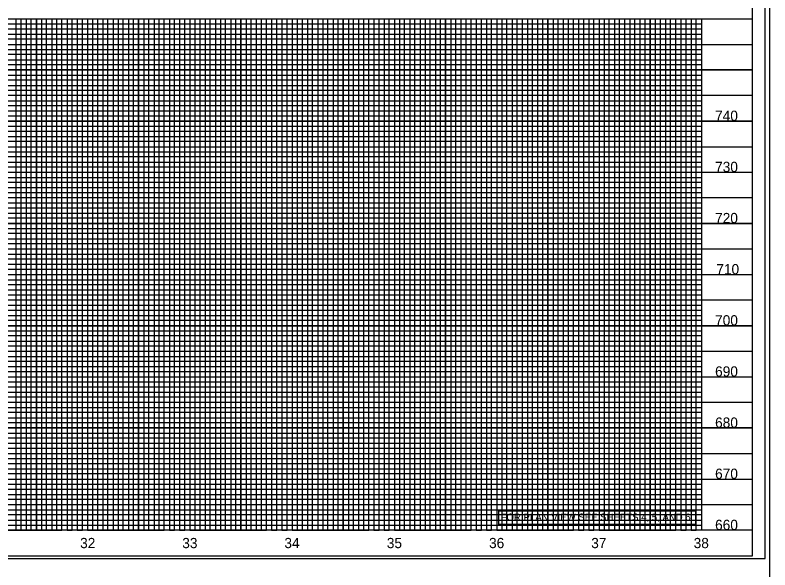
# Model space of a CAD drawing. Extents: x 1754992 to 1757273, y 732111 to 735411.
# Drawn here: x 1756127 to 1756865, y 734322 to 734864 of the extents above; entities that cross this region are included whole.
import ezdxf

# ---------------------------------------------------------------- set-up
doc = ezdxf.new("R2010")
doc.units = 0
for name, color, linetype in [('ENG SEALS CELL', 7, 'Continuous'), ('Prop DSN Text', 7, 'Continuous'), ('Scratch_Level_3', 7, 'Continuous'), ('Sheet DOT Grid CELL', 7, 'Continuous'), ('Sheet PE Seal Cell', 7, 'Continuous'), ('Sheet Plot Border Inside CELL', 7, 'Continuous'), ('Sheet Plot Border Outside CELL', 7, 'Continuous'), ('Sheet Profile CELL', 7, 'Continuous'), ('Sheet Profile Grid Major CELL', 7, 'Continuous'), ('Sheet Profile Grid Middle CELL', 7, 'Continuous'), ('Sheet Profile Grid Minor CELL', 7, 'Continuous')]:
    doc.layers.add(name, color=color, linetype=linetype)

msp = doc.modelspace()

# ---------------------------------------------------------------- linework, layer by layer
at = {"layer": 'ENG SEALS CELL'}
msp.add_lwpolyline([(1756599.59, 734379.75), (1756792.01, 734379.75), (1756792.01, 734366.55), (1756599.59, 734366.55)], close=True, dxfattribs=at)
at = {"layer": 'Scratch_Level_3'}
msp.add_lwpolyline([(1755397.67, 734860.78), (1756797.67, 734860.78), (1756797.67, 734360.78), (1755397.67, 734360.78)], close=True, dxfattribs=at)
at = {"layer": 'Sheet DOT Grid CELL'}
for p, q in [((1755347.67, 734860.78), (1756847.56, 734860.78)), ((1756147.67, 734860.78), (1756147.67, 734360.78)), ((1756197.67, 734860.78), (1756197.67, 734360.78)), ((1756247.67, 734860.78), (1756247.67, 734360.78)), ((1756297.67, 734860.78), (1756297.67, 734360.78)), ((1756347.67, 734860.78), (1756347.67, 734360.78)), ((1756397.67, 734860.78), (1756397.67, 734360.78)), ((1756447.67, 734860.78), (1756447.67, 734360.78)), ((1756497.67, 734860.78), (1756497.67, 734360.78)), ((1756547.67, 734860.78), (1756547.67, 734360.78)), ((1756597.67, 734860.78), (1756597.67, 734360.78)), ((1756647.67, 734860.78), (1756647.67, 734360.78)), ((1756697.67, 734860.78), (1756697.67, 734360.78)), ((1756747.67, 734860.78), (1756747.67, 734360.78)), ((1756797.67, 734860.78), (1756797.67, 734360.78)), ((1755347.67, 734810.78), (1756847.56, 734810.78)), ((1755347.67, 734760.78), (1756847.56, 734760.78)), ((1755347.67, 734710.78), (1756847.56, 734710.78)), ((1755347.67, 734660.78), (1756847.56, 734660.78)), ((1755347.67, 734610.78), (1756847.56, 734610.78)), ((1755347.67, 734560.78), (1756847.56, 734560.78)), ((1755347.67, 734510.78), (1756847.56, 734510.78)), ((1755347.67, 734460.78), (1756847.56, 734460.78)), ((1755347.67, 734410.78), (1756847.56, 734410.78))]:
    msp.add_line(p, q, dxfattribs=at)
at = {"layer": 'Sheet Plot Border Inside CELL'}
msp.add_lwpolyline([(1755193.67, 734333.23), (1756860.17, 734333.23), (1756860.17, 735388.33), (1755193.67, 735388.33)], close=True, dxfattribs=at)
at = {"layer": 'Sheet Plot Border Outside CELL'}
msp.add_lwpolyline([(1755180.67, 734310.78), (1756864.67, 734310.78), (1756864.67, 735410.78), (1755180.67, 735410.78)], close=True, dxfattribs=at)
at = {"layer": 'Sheet Profile CELL'}
for p, q in [((1755347.67, 734860.78), (1756847.67, 734860.78)), ((1756847.67, 734360.78), (1755347.67, 734360.78)), ((1755347.67, 734335.78), (1756847.67, 734335.78))]:
    msp.add_line(p, q, dxfattribs=at)
msp.add_lwpolyline([(1756847.67, 735385.78), (1755347.67, 735385.78), (1755347.67, 734335.78), (1756847.67, 734335.78)], close=True, dxfattribs=at)
at = {"layer": 'Sheet Profile Grid Major CELL'}
for p, q in [((1756147.67, 734860.78), (1756197.67, 734860.78)), ((1756247.67, 734860.78), (1756297.67, 734860.78)), ((1756347.67, 734860.78), (1756397.67, 734860.78)), ((1756447.67, 734860.78), (1756497.67, 734860.78)), ((1756547.67, 734860.78), (1756597.67, 734860.78)), ((1756647.67, 734860.78), (1756697.67, 734860.78)), ((1756747.67, 734860.78), (1756797.67, 734860.78)), ((1756747.67, 734360.78), (1756747.67, 734360.78))]:
    msp.add_line(p, q, dxfattribs=at)
for points in [[(1756097.67, 734360.78), (1756147.67, 734360.78), (1756147.67, 734860.78), (1756197.67, 734860.78), (1756197.67, 734360.78), (1756247.67, 734360.78), (1756247.67, 734860.78), (1756297.67, 734860.78), (1756297.67, 734360.78), (1756347.67, 734360.78), (1756347.67, 734860.78), (1756397.67, 734860.78), (1756397.67, 734360.78), (1756447.67, 734360.78), (1756447.67, 734860.78), (1756497.67, 734860.78), (1756497.67, 734360.78), (1756547.67, 734360.78), (1756547.67, 734860.78), (1756597.67, 734860.78), (1756597.67, 734360.78), (1756647.67, 734360.78), (1756647.67, 734860.78), (1756697.67, 734860.78), (1756697.67, 734360.78), (1756747.67, 734360.78), (1756747.67, 734360.78), (1756747.67, 734860.78), (1756797.67, 734860.78), (1756797.67, 734360.78)], [(1756847.67, 734810.78), (1755347.67, 734810.78)], [(1756847.67, 734760.78), (1755347.67, 734760.78), (1755347.67, 734710.78), (1756847.67, 734710.78)], [(1756847.67, 734660.78), (1755347.67, 734660.78), (1755347.67, 734610.78), (1756847.67, 734610.78)], [(1756847.67, 734560.78), (1755347.67, 734560.78), (1755347.67, 734510.78), (1756847.67, 734510.78)], [(1756847.67, 734460.78), (1755347.67, 734460.78), (1755347.67, 734460.78), (1755347.67, 734410.78), (1756847.67, 734410.78)], [(1756847.67, 734360.78), (1755347.67, 734360.78)]]:
    msp.add_lwpolyline(points, dxfattribs=at)
at = {"layer": 'Sheet Profile Grid Middle CELL'}
for points in [[(1756122.67, 734360.78), (1756172.67, 734360.78), (1756172.67, 734860.78), (1756222.67, 734860.78), (1756222.67, 734360.78), (1756272.67, 734360.78), (1756272.67, 734860.78), (1756322.67, 734860.78), (1756322.67, 734360.78), (1756372.67, 734360.78), (1756372.67, 734860.78), (1756422.67, 734860.78), (1756422.67, 734360.78), (1756472.67, 734360.78), (1756472.67, 734860.78), (1756522.67, 734860.78), (1756522.67, 734360.78), (1756572.67, 734360.78), (1756572.67, 734860.78), (1756622.67, 734860.78), (1756622.67, 734360.78), (1756672.67, 734360.78), (1756672.67, 734860.78), (1756722.67, 734860.78), (1756722.67, 734360.78), (1756772.67, 734360.78), (1756772.67, 734860.78)], [(1755347.67, 734835.78), (1756847.67, 734835.78)], [(1756847.67, 734785.78), (1755347.67, 734785.78), (1755347.67, 734735.78), (1756847.67, 734735.78)], [(1756847.67, 734685.78), (1755347.67, 734685.78), (1755347.67, 734635.78), (1756847.67, 734635.78)], [(1756847.67, 734585.78), (1755347.67, 734585.78), (1755347.67, 734535.78), (1756847.67, 734535.78)], [(1756847.67, 734485.78), (1755347.67, 734485.78), (1755347.67, 734435.78), (1756847.67, 734435.78)], [(1756847.67, 734385.78), (1755347.67, 734385.78)]]:
    msp.add_lwpolyline(points, dxfattribs=at)
at = {"layer": 'Sheet Profile Grid Minor CELL'}
for p, q in [((1755397.67, 734855.78), (1756797.67, 734855.78)), ((1756797.67, 734850.78), (1755397.67, 734850.78)), ((1755397.67, 734845.78), (1756797.67, 734845.78)), ((1756797.67, 734840.78), (1755397.67, 734840.78)), ((1755397.67, 734830.78), (1756797.67, 734830.78)), ((1756797.67, 734825.78), (1755397.67, 734825.78)), ((1755397.67, 734820.78), (1756797.67, 734820.78)), ((1756797.67, 734815.78), (1755397.67, 734815.78)), ((1755397.67, 734805.78), (1756797.67, 734805.78)), ((1756797.67, 734800.78), (1755397.67, 734800.78)), ((1755397.67, 734795.78), (1756797.67, 734795.78)), ((1756797.67, 734790.78), (1755397.67, 734790.78)), ((1755397.67, 734780.78), (1756797.67, 734780.78)), ((1756797.67, 734775.78), (1755397.67, 734775.78)), ((1755397.67, 734770.78), (1756797.67, 734770.78)), ((1756797.67, 734765.78), (1755397.67, 734765.78)), ((1755397.67, 734755.78), (1756797.67, 734755.78)), ((1756797.67, 734750.78), (1755397.67, 734750.78)), ((1755397.67, 734745.78), (1756797.67, 734745.78)), ((1756797.67, 734740.78), (1755397.67, 734740.78)), ((1755397.67, 734730.78), (1756797.67, 734730.78)), ((1756797.67, 734725.78), (1755397.67, 734725.78)), ((1755397.67, 734720.78), (1756797.67, 734720.78)), ((1756797.67, 734715.78), (1755397.67, 734715.78)), ((1755397.67, 734705.78), (1756797.67, 734705.78)), ((1756797.67, 734700.78), (1755397.67, 734700.78)), ((1755397.67, 734695.78), (1756797.67, 734695.78)), ((1756797.67, 734690.78), (1755397.67, 734690.78)), ((1755397.67, 734680.78), (1756797.67, 734680.78)), ((1756797.67, 734675.78), (1755397.67, 734675.78)), ((1755397.67, 734670.78), (1756797.67, 734670.78)), ((1756797.67, 734665.78), (1755397.67, 734665.93)), ((1755397.67, 734655.78), (1756797.67, 734655.78)), ((1756797.67, 734650.78), (1755397.67, 734650.78)), ((1755397.67, 734645.78), (1756797.67, 734645.78)), ((1756797.67, 734640.78), (1755397.67, 734640.78)), ((1755397.67, 734630.78), (1756797.67, 734630.78)), ((1756797.67, 734625.78), (1755397.67, 734625.78)), ((1755397.67, 734620.78), (1756797.67, 734620.78)), ((1756797.67, 734615.78), (1755397.67, 734615.78)), ((1755397.67, 734605.78), (1756797.67, 734605.78)), ((1756797.67, 734600.78), (1755397.67, 734600.78)), ((1755397.67, 734595.78), (1756797.67, 734595.78)), ((1756797.67, 734590.78), (1755397.67, 734590.78)), ((1755397.67, 734580.78), (1756797.67, 734580.78)), ((1756797.67, 734575.78), (1755397.67, 734575.78)), ((1755397.67, 734570.78), (1756797.67, 734570.78)), ((1756797.67, 734565.78), (1755397.67, 734565.78)), ((1755397.67, 734555.78), (1756797.67, 734555.78)), ((1756797.67, 734550.78), (1755397.67, 734550.78)), ((1755397.67, 734545.78), (1756797.67, 734545.78)), ((1756797.67, 734540.78), (1755397.67, 734540.78)), ((1755397.67, 734530.78), (1756797.67, 734530.78)), ((1756797.67, 734525.78), (1755397.67, 734525.78)), ((1755397.67, 734520.78), (1756797.67, 734520.78)), ((1756797.67, 734515.78), (1755397.67, 734515.78)), ((1755397.67, 734505.78), (1756797.67, 734505.78)), ((1756797.67, 734500.78), (1755397.67, 734500.78)), ((1755397.67, 734495.78), (1756797.67, 734495.78)), ((1756797.67, 734490.78), (1755397.67, 734490.78)), ((1755397.67, 734480.78), (1756797.67, 734480.78)), ((1756797.67, 734475.78), (1755397.67, 734475.78)), ((1755397.67, 734470.78), (1756797.67, 734470.78)), ((1756797.67, 734465.78), (1755397.67, 734465.78)), ((1755397.67, 734455.78), (1756797.67, 734455.78)), ((1756797.67, 734450.78), (1755397.67, 734450.78)), ((1755397.67, 734445.78), (1756797.67, 734445.78)), ((1756797.67, 734440.78), (1755397.67, 734440.78)), ((1755397.67, 734430.78), (1756797.67, 734430.78)), ((1756797.67, 734425.78), (1755397.67, 734425.78)), ((1755397.67, 734420.78), (1756797.67, 734420.78)), ((1756797.67, 734415.78), (1755397.67, 734415.78)), ((1755397.67, 734405.78), (1756797.67, 734405.78)), ((1756797.67, 734400.78), (1755397.67, 734400.78)), ((1755397.67, 734395.78), (1756797.67, 734395.78)), ((1756797.67, 734390.78), (1755397.67, 734390.78)), ((1755397.67, 734380.78), (1756797.67, 734380.78)), ((1756797.67, 734375.78), (1755397.67, 734375.78)), ((1755397.67, 734370.78), (1756797.67, 734370.78)), ((1755397.67, 734365.78), (1756797.67, 734365.78)), ((1756797.67, 734365.78), (1756797.67, 734365.78))]:
    msp.add_line(p, q, dxfattribs=at)
for points in [[(1756117.67, 734860.78), (1756127.67, 734860.78), (1756127.67, 734360.78), (1756132.67, 734360.78), (1756132.67, 734860.78), (1756137.67, 734860.78), (1756137.67, 734360.78), (1756142.67, 734360.78), (1756142.67, 734860.78), (1756152.67, 734860.78), (1756152.67, 734360.78), (1756157.67, 734360.78), (1756157.67, 734860.78), (1756162.67, 734860.78), (1756162.67, 734360.78), (1756167.67, 734360.78), (1756167.67, 734860.78), (1756177.67, 734860.78), (1756177.67, 734360.78), (1756182.67, 734360.78), (1756182.67, 734860.78), (1756187.67, 734860.78), (1756187.67, 734360.78), (1756192.67, 734360.78), (1756192.67, 734860.78), (1756202.67, 734860.78), (1756202.67, 734360.78), (1756207.37, 734361.33), (1756207.67, 734360.78), (1756207.67, 734860.78), (1756212.67, 734860.78), (1756212.67, 734360.78), (1756217.67, 734360.78), (1756217.67, 734860.78), (1756227.67, 734860.78), (1756227.67, 734360.78), (1756232.67, 734360.78)], [(1756232.67, 734360.78), (1756232.67, 734860.78), (1756237.67, 734860.78), (1756237.67, 734360.78), (1756242.67, 734360.78), (1756242.67, 734860.78), (1756252.67, 734860.78), (1756252.67, 734360.78), (1756257.67, 734360.78), (1756257.67, 734860.78), (1756262.67, 734860.78), (1756262.67, 734360.78), (1756267.67, 734360.78), (1756267.67, 734860.78), (1756277.67, 734860.78), (1756277.67, 734360.78), (1756282.67, 734360.78), (1756282.67, 734860.78), (1756287.67, 734860.78), (1756287.67, 734360.78), (1756292.67, 734360.78), (1756292.67, 734860.78), (1756302.67, 734860.78), (1756302.67, 734360.78), (1756307.67, 734360.78), (1756307.67, 734860.78), (1756312.67, 734860.78), (1756312.67, 734360.78), (1756317.67, 734360.78), (1756317.67, 734860.78), (1756327.67, 734860.78), (1756327.67, 734360.78), (1756332.67, 734360.78), (1756332.67, 734860.78), (1756337.67, 734860.78), (1756337.67, 734360.78), (1756342.67, 734360.78), (1756342.67, 734860.78), (1756352.67, 734860.78), (1756352.67, 734360.78), (1756357.67, 734360.78), (1756357.67, 734860.78), (1756362.67, 734860.78), (1756362.67, 734360.78), (1756367.67, 734360.78), (1756367.67, 734860.78), (1756377.67, 734860.78), (1756377.67, 734360.78), (1756382.67, 734360.78), (1756382.67, 734860.78), (1756387.67, 734860.78), (1756387.67, 734360.78), (1756392.67, 734360.78), (1756392.67, 734860.78), (1756402.67, 734860.78), (1756402.67, 734360.78), (1756407.67, 734360.78), (1756407.67, 734860.78), (1756412.67, 734860.78), (1756412.67, 734360.78), (1756417.67, 734360.78), (1756417.67, 734860.78), (1756427.67, 734860.78), (1756427.67, 734360.78), (1756432.67, 734360.78), (1756432.67, 734860.78), (1756437.67, 734860.78), (1756437.67, 734360.78), (1756442.67, 734360.78), (1756442.67, 734860.78), (1756452.67, 734860.78), (1756452.67, 734360.78), (1756457.67, 734360.78), (1756457.67, 734860.78), (1756462.67, 734860.78), (1756462.67, 734360.78), (1756467.67, 734360.78), (1756467.67, 734860.78), (1756477.67, 734860.78), (1756477.67, 734360.78), (1756482.67, 734360.78), (1756482.67, 734860.78), (1756487.67, 734860.78), (1756487.67, 734360.78), (1756492.67, 734360.78), (1756492.67, 734860.78), (1756502.67, 734860.78), (1756502.67, 734360.78), (1756507.67, 734360.78), (1756507.67, 734860.78), (1756512.67, 734860.78), (1756512.67, 734360.78), (1756517.67, 734360.78), (1756517.67, 734860.78), (1756527.67, 734860.78), (1756527.67, 734360.78), (1756532.67, 734360.78), (1756532.67, 734860.78), (1756537.67, 734860.78), (1756537.67, 734360.78)], [(1756537.67, 734360.78), (1756542.67, 734360.78), (1756542.67, 734860.78), (1756552.67, 734860.78), (1756552.67, 734360.78), (1756557.67, 734360.78), (1756557.67, 734860.78), (1756562.67, 734860.78), (1756562.67, 734360.78), (1756567.67, 734360.78), (1756567.67, 734860.78), (1756577.67, 734860.78), (1756577.67, 734360.78), (1756582.67, 734360.78), (1756582.67, 734860.78), (1756587.67, 734860.78), (1756587.67, 734360.78), (1756592.67, 734360.78), (1756592.67, 734860.78), (1756602.67, 734860.78), (1756602.67, 734360.78), (1756607.67, 734360.78), (1756607.67, 734860.78), (1756612.67, 734860.78), (1756612.67, 734360.78), (1756617.67, 734360.78), (1756617.67, 734860.78), (1756627.67, 734860.78), (1756627.67, 734360.78), (1756632.67, 734360.78), (1756632.67, 734860.78), (1756637.67, 734860.78), (1756637.67, 734360.78), (1756642.67, 734360.78), (1756642.67, 734860.78), (1756652.67, 734860.78), (1756652.67, 734360.78), (1756657.67, 734360.78), (1756657.67, 734860.78), (1756662.67, 734860.78), (1756662.67, 734360.78), (1756667.67, 734360.78), (1756667.67, 734860.78), (1756677.67, 734860.78), (1756677.67, 734360.78), (1756682.67, 734360.78), (1756682.67, 734860.78), (1756687.67, 734860.78), (1756687.67, 734360.78), (1756692.67, 734360.78), (1756692.67, 734860.78), (1756702.67, 734860.78), (1756702.67, 734360.78), (1756707.67, 734360.78), (1756707.67, 734860.78), (1756712.67, 734860.78), (1756712.67, 734360.78), (1756717.67, 734360.78), (1756717.67, 734860.78), (1756727.67, 734860.78), (1756727.67, 734360.78), (1756732.67, 734360.78), (1756732.67, 734860.78), (1756737.67, 734860.78), (1756737.67, 734360.78), (1756742.67, 734360.78), (1756742.67, 734860.78), (1756752.67, 734860.78), (1756752.67, 734360.78), (1756757.67, 734360.78), (1756757.67, 734860.78), (1756762.67, 734860.78), (1756762.67, 734360.78), (1756767.67, 734360.78), (1756767.67, 734860.78), (1756777.67, 734860.78), (1756777.67, 734360.78), (1756782.67, 734360.78), (1756782.67, 734860.78), (1756787.67, 734860.78), (1756787.67, 734360.78), (1756792.67, 734360.78), (1756792.67, 734860.78), (1756797.67, 734860.78)]]:
    msp.add_lwpolyline(points, dxfattribs=at)

# ---------------------------------------------------------------- texts
at = {"layer": 'Prop DSN Text'}
for s, p in [('740', (1756811.1, 734761.03)), ('730', (1756811.1, 734711.03)), ('720', (1756811.1, 734661.03)), ('710', (1756812.3, 734611.03)), ('700', (1756811.1, 734561.03)), ('690', (1756811.1, 734511.03)), ('680', (1756811.1, 734461.03)), ('670', (1756811.1, 734411.03)), ('660', (1756811.1, 734361.03))]:
    msp.add_text(s, height=10, dxfattribs=at).set_placement(p)
at = {"layer": 'Scratch_Level_3'}
for s, p in [('32', (1756190.44, 734343.28)), ('33', (1756290.28, 734343.28)), ('34', (1756390.12, 734343.28)), ('35', (1756490.21, 734343.28)), ('36', (1756590.15, 734343.28)), ('37', (1756690.01, 734343.28)), ('38', (1756790.14, 734343.28))]:
    msp.add_text(s, height=10, dxfattribs=at).set_placement(p)
at = {"layer": 'Sheet PE Seal Cell'}
msp.add_text('FOR PLAN VIEW SEE SHEETS 4, 5, AND 6', height=7, dxfattribs=at).set_placement((1756601.53, 734370.13))

doc.saveas('drawing.dxf')
